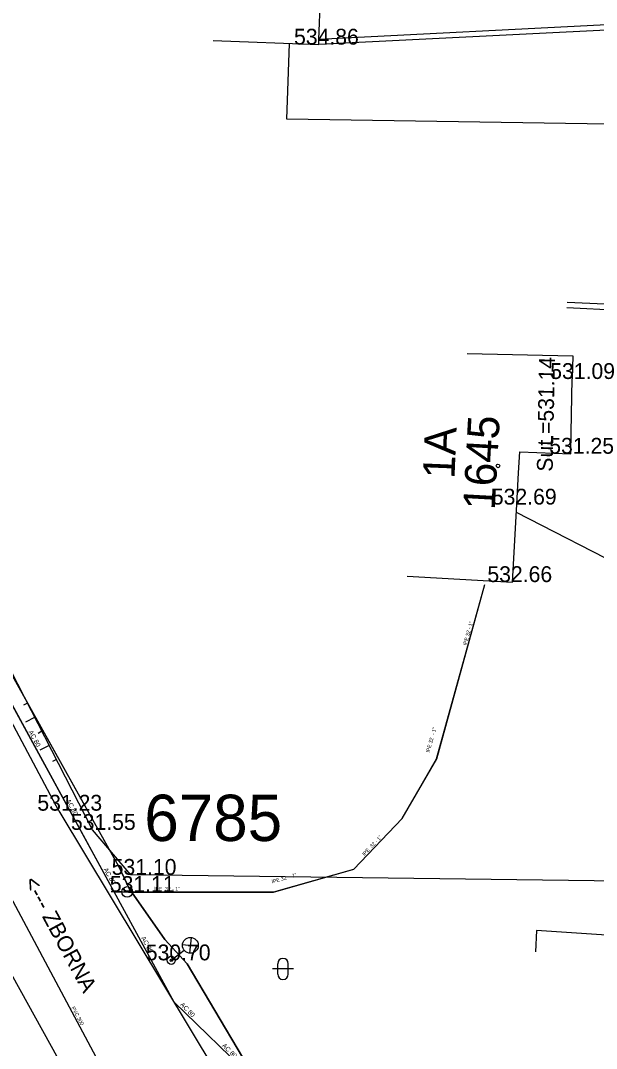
# Model space of a CAD drawing. Extents: x -669393 to -668650, y -1126925 to -1126294.
# Drawn here: x -669014.21 to -668986.94, y -1126777.26 to -1126728.57 of the extents above; entities that cross this region are included whole.
import ezdxf

# ---------------------------------------------------------------- set-up
doc = ezdxf.new("R2010")
doc.units = 0
for name, color, linetype in [('G_Bod_tecka', 7, 'Continuous'), ('G_Bod_vyska', 7, 'Continuous'), ('G_Budovy-znacky', 7, 'Continuous'), ('G_Budovy_Objekty', 7, 'Continuous'), ('G_Budovy_vstupy', 7, 'Continuous'), ('G_Cisla_orientacni', 7, 'Continuous'), ('G_Cisla_popisna', 7, 'Continuous'), ('G_Objekty_technicke', 7, 'Continuous'), ('G_Plochy_zpevnene', 7, 'Continuous'), ('G_Ploty', 7, 'Continuous'), ('G_Poznamky_odkaz', 7, 'Continuous'), ('G_Site-vodovod', 7, 'Continuous'), ('G_Vyskove_srafy', 7, 'Continuous'), ('G_Z_ELsilove_podz_kotovane', 7, 'Continuous'), ('G_Z_KANAL_podz_kotovane', 7, 'Continuous'), ('G_Z_PLYNY_podz_priblizne', 7, 'Continuous'), ('G_Z_SPOJE_podz_geodeticky', 7, 'Continuous'), ('G_Z_SPOJE_podz_kotovane', 7, 'Continuous'), ('G_Z_SPOJE_podz_priblizne', 7, 'Continuous'), ('G_Z_VODA_podz_kotovane', 7, 'Continuous'), ('G_Zelen-Znacky', 7, 'Continuous'), ('Vrstva 1', 7, 'Continuous'), ('Vrstva 12', 7, 'Continuous'), ('Vrstva 25', 7, 'Continuous'), ('Vrstva 27', 7, 'Continuous'), ('Vrstva 3', 7, 'Continuous'), ('Vrstva 4', 7, 'Continuous'), ('Vrstva 6', 7, 'Continuous'), ('Vrstva 62', 7, 'Continuous')]:
    doc.layers.add(name, color=color, linetype=linetype)

msp = doc.modelspace()

# ---------------------------------------------------------------- linework, layer by layer
at = {"layer": 'G_Bod_tecka'}
for p, q in [((-669000.08, -1126729.71), (-669000.08, -1126729.71)), ((-668988.08, -1126745.55), (-668988.08, -1126745.55)), ((-668988.15, -1126749.09), (-668988.15, -1126749.09)), ((-668990.71, -1126751.5), (-668990.71, -1126751.5)), ((-668990.91, -1126755.17), (-668990.91, -1126755.17)), ((-669012.39, -1126766), (-669012.39, -1126766)), ((-669010.8, -1126766.91), (-669010.8, -1126766.91)), ((-669008.99, -1126769.04), (-669008.99, -1126769.04)), ((-669009.16, -1126769.85), (-669009.16, -1126769.85)), ((-669007.07, -1126773.09), (-669007.07, -1126773.09))]:
    msp.add_line(p, q, dxfattribs=at)
at = {"layer": 'G_Budovy-znacky'}
msp.add_circle((-668991.6, -1126749.67), 0.0875, dxfattribs=at)
at = {"layer": 'G_Budovy_Objekty'}
for p, q in [((-669000.08, -1126729.46), (-668999.64, -1126718.94)), ((-669000.08, -1126729.71), (-669000.08, -1126729.46)), ((-669005.08, -1126729.51), (-669000.08, -1126729.71)), ((-668993.06, -1126744.35), (-668988.06, -1126744.45)), ((-668988.06, -1126744.45), (-668988.08, -1126745.55)), ((-668988.15, -1126749.09), (-668988.13, -1126748.09)), ((-668990.63, -1126750), (-668990.57, -1126749)), ((-668990.57, -1126749), (-668988.15, -1126749.09)), ((-668990.91, -1126755.17), (-668990.71, -1126751.5)), ((-668995.9, -1126754.89), (-668990.91, -1126755.17))]:
    msp.add_line(p, q, dxfattribs=at)
at = {"layer": 'G_Budovy_vstupy'}
for p, q in [((-668988.13, -1126748.09), (-668988.08, -1126745.55)), ((-668990.71, -1126751.5), (-668990.63, -1126750))]:
    msp.add_line(p, q, dxfattribs=at)
at = {"layer": 'G_Objekty_technicke'}
for points in [[(-669006.538, -1126772.335), (-669005.793, -1126772.425)], [(-669006.121, -1126772.008), (-669006.21, -1126772.752)], [(-669007.07, -1126773.09), (-669006.46, -1126772.611)]]:
    msp.add_lwpolyline(points, dxfattribs=at)
for centre, radius in [((-669006.166, -1126772.38), 0.375), ((-669007.07, -1126773.09), 0.19), ((-669007.07, -1126773.09), 0.05)]:
    msp.add_circle(centre, radius, dxfattribs=at)
at = {"layer": 'G_Plochy_zpevnene'}
for p, q in [((-669012.39, -1126766), (-669002.18, -1126783)), ((-669005.94, -1126789.45), (-669016.35, -1126770.66))]:
    msp.add_line(p, q, dxfattribs=at)
msp.add_lwpolyline([(-669012.39, -1126766), (-669017.9, -1126755.66)], dxfattribs=at)
at = {"layer": 'G_Ploty'}
for p, q in [((-668981.91, -1126728.54), (-669000.08, -1126729.46)), ((-668981.69, -1126728.78), (-669000.08, -1126729.71)), ((-668983.56, -1126742.15), (-668988.32, -1126741.92)), ((-668988.34, -1126742.17), (-668983.59, -1126742.4)), ((-669010.8, -1126766.91), (-669016.73, -1126755.36)), ((-669008.99, -1126769.04), (-669010.8, -1126766.91)), ((-668985.43, -1126769.34), (-669008.99, -1126769.04))]:
    msp.add_line(p, q, dxfattribs=at)
at = {"layer": 'G_Site-vodovod'}
for points in [[(-669009.41, -1126769.85), (-669009.91, -1126769.85)], [(-669008.91, -1126769.85), (-669008.41, -1126769.85)]]:
    msp.add_lwpolyline(points, dxfattribs=at)
msp.add_circle((-669009.16, -1126769.85), 0.25, dxfattribs=at)
at = {"layer": 'G_Vyskove_srafy'}
for points in [[(-669013.88, -1126760.91), (-669014.06, -1126761)], [(-669013.54, -1126761.58), (-669013.98, -1126761.81)], [(-669013.2, -1126762.24), (-669013.38, -1126762.34)], [(-669012.85, -1126762.91), (-669013.3, -1126763.14)], [(-669012.51, -1126763.58), (-669012.69, -1126763.67)]]:
    msp.add_lwpolyline(points, dxfattribs=at)
at = {"layer": 'G_Z_ELsilove_podz_kotovane'}
msp.add_lwpolyline([(-668991.15, -1126787.71), (-668992.47, -1126784.68), (-668992.94, -1126784.14), (-668993.85, -1126784), (-668994.99, -1126783.88), (-668997.24, -1126783.28), (-668999.66, -1126783.12), (-669000.56, -1126782.76), (-669001.95, -1126780.63), (-669003.7, -1126777.68), (-669006.31, -1126773.26), (-669007.38, -1126772.1), (-669009.06, -1126769.68), (-669009.55, -1126768.64), (-669025.04, -1126740.9), (-669039.34, -1126713.66), (-669057.59, -1126688.86), (-669057.53, -1126686.66), (-669073.8, -1126662.04), (-669088.6, -1126634.97), (-669111.98, -1126614.96), (-669163.86, -1126582.84), (-669189.05, -1126566.12), (-669226.41, -1126541.64)], dxfattribs=at)
at = {"layer": 'G_Z_KANAL_podz_kotovane'}
msp.add_lwpolyline([(-669021.5, -1126757.31), (-669019.78, -1126760.55), (-669002.4, -1126793.12), (-668998.38, -1126800.66), (-668997.87, -1126801.61)], dxfattribs=at)
at = {"layer": 'G_Z_PLYNY_podz_priblizne'}
msp.add_lwpolyline([(-668983.17, -1126772.12), (-668989.77, -1126771.68), (-668989.83, -1126772.68)], dxfattribs=at)
at = {"layer": 'G_Z_SPOJE_podz_geodeticky'}
for points in [[(-669001.6, -1126733.24), (-669001.48, -1126729.66)], [(-668982.59, -1126754.6), (-668982.04, -1126748.5), (-668981.76, -1126746.81), (-668980.27, -1126733.58), (-669001.6, -1126733.24)], [(-668982.59, -1126754.6), (-668985.31, -1126754.66), (-668990.73, -1126751.88)]]:
    msp.add_lwpolyline(points, dxfattribs=at)
at = {"layer": 'G_Z_SPOJE_podz_kotovane'}
for points in [[(-669001.6, -1126733.24), (-669001.48, -1126729.66)], [(-668982.59, -1126754.6), (-668982.04, -1126748.5), (-668981.76, -1126746.81), (-668980.27, -1126733.58), (-669001.6, -1126733.24)], [(-668982.59, -1126754.6), (-668985.31, -1126754.66), (-668990.73, -1126751.88)]]:
    msp.add_lwpolyline(points, dxfattribs=at)
at = {"layer": 'G_Z_SPOJE_podz_priblizne'}
for points in [[(-669001.6, -1126733.24), (-669001.48, -1126729.66)], [(-668982.59, -1126754.6), (-668982.04, -1126748.5), (-668981.76, -1126746.81), (-668980.27, -1126733.58), (-669001.6, -1126733.24)], [(-668982.59, -1126754.6), (-668985.31, -1126754.66), (-668990.73, -1126751.88)]]:
    msp.add_lwpolyline(points, dxfattribs=at)
at = {"layer": 'G_Z_VODA_podz_kotovane'}
for points in [[(-668985.62, -1126791.74), (-668992.01, -1126788.5), (-668997.53, -1126784.21), (-669003.22, -1126778.68), (-669006.93, -1126775.07), (-669009.78, -1126769.85), (-669016.27, -1126757.96), (-669026.17, -1126739.37), (-669033.16, -1126727.07), (-669036.74, -1126721.2), (-669037.32, -1126720.23), (-669038.2, -1126718.75), (-669038.67, -1126717.89)], [(-669009.78, -1126769.85), (-669009.1, -1126769.85), (-669008.97, -1126769.85), (-669002.22, -1126769.85), (-668998.42, -1126768.77), (-668996.14, -1126766.37), (-668994.5, -1126763.54), (-668992.22, -1126755.28)]]:
    msp.add_lwpolyline(points, dxfattribs=at)
at = {"layer": 'G_Zelen-Znacky'}
for points in [[(-669002.03, -1126773.75), (-669002.03, -1126773.25)], [(-669001.53, -1126773.75), (-669001.53, -1126773.25)], [(-669001.28, -1126773.5), (-669002.28, -1126773.5)]]:
    msp.add_lwpolyline(points, dxfattribs=at)
for centre, start, end in [((-669001.78, -1126773.25), 0, 180), ((-669001.78, -1126773.75), 180, 0)]:
    msp.add_arc(centre, 0.25, start, end, dxfattribs=at)
at = {"layer": 'Vrstva 1'}
msp.add_line((-669009.55, -1126768.64), (-669009.55, -1126768.64), dxfattribs=at)
at = {"layer": 'Vrstva 12'}
msp.add_lwpolyline([(-669021.5, -1126757.31), (-669019.78, -1126760.55), (-669002.4, -1126793.125), (-668998.377, -1126800.659), (-668997.87, -1126801.61)], dxfattribs=at)
at = {"layer": 'Vrstva 25'}
msp.add_lwpolyline([(-669009.778, -1126769.852), (-669009.1, -1126769.854), (-669008.966, -1126769.854), (-669002.225, -1126769.854), (-668998.419, -1126768.766), (-668996.136, -1126766.373), (-668994.505, -1126763.545), (-668992.221, -1126755.279)], dxfattribs=at)
at = {"layer": 'Vrstva 27'}
msp.add_lwpolyline([(-668985.623, -1126791.742), (-668992.014, -1126788.499), (-668997.526, -1126784.214), (-669003.219, -1126778.678), (-669006.931, -1126775.068), (-669009.778, -1126769.852), (-669016.269, -1126757.96), (-669026.168, -1126739.368), (-669033.16, -1126727.07), (-669036.741, -1126721.201), (-669037.32, -1126720.228), (-669038.2, -1126718.75), (-669038.665, -1126717.892)], dxfattribs=at)
at = {"layer": 'Vrstva 6'}
msp.add_line((-669009.1, -1126769.854), (-669009.1, -1126769.854), dxfattribs=at)
at = {"layer": 'Vrstva 62'}
for p, q in [((-669009.55, -1126768.64), (-669025.04, -1126740.9)), ((-669009.06, -1126769.68), (-669009.55, -1126768.64)), ((-669009.55, -1126768.64), (-669009.06, -1126769.68)), ((-669007.38, -1126772.1), (-669009.06, -1126769.68)), ((-669009.06, -1126769.68), (-669007.38, -1126772.1)), ((-669006.31, -1126773.26), (-669007.38, -1126772.1)), ((-669007.38, -1126772.1), (-669006.31, -1126773.26)), ((-669003.7, -1126777.68), (-669006.31, -1126773.26)), ((-669006.31, -1126773.26), (-669003.7, -1126777.68))]:
    msp.add_line(p, q, dxfattribs=at)

# ---------------------------------------------------------------- texts
at = {"layer": 'G_Bod_vyska'}
for s, p in [('534.86', (-669001.258, -1126729.71)), ('531.09', (-668989.126, -1126745.55)), ('531.25', (-668989.172, -1126749.09)), ('532.69', (-668991.89, -1126751.5)), ('532.66', (-668992.102, -1126755.17)), ('531.23', (-669013.412, -1126766)), ('531.55', (-669011.822, -1126766.91)), ('531.10', (-669009.892, -1126769.04)), ('531.11', (-669009.979, -1126769.85)), ('530.70', (-669008.277, -1126773.09))]:
    msp.add_text(s, height=0.75, dxfattribs=at).set_placement(p)
at = {"layer": 'G_Cisla_orientacni'}
msp.add_text('1A', height=1.5, rotation=87.6291, dxfattribs=at).set_placement((-668993.661, -1126750.295))
at = {"layer": 'G_Cisla_popisna'}
msp.add_text('1645', height=1.5, rotation=86.8613, dxfattribs=at).set_placement((-668991.756, -1126751.775))
at = {"layer": 'G_Poznamky_odkaz'}
for s, rotation, p in [('Sut.=531.14', 88.8723, (-668989.01, -1126749.946)), ('<--- ZBORNA', 298.3262, (-669014.09, -1126769.366))]:
    msp.add_text(s, height=0.75, rotation=rotation, dxfattribs=at).set_placement(p)
at = {"layer": 'Vrstva 3'}
msp.add_text('PVC 300', height=0.1755, rotation=298.0545, dxfattribs=at).set_placement((-669011.807, -1126775.335))
at = {"layer": 'Vrstva 4'}
for s, height, rotation, p in [('lPE 32 - 1"', 0.17551, 74.5939, (-668993.086, -1126758.173)), ('lPE 32  - 1"', 0.17551, 74.3578, (-668994.842, -1126763.254)), ('AC 80', 0.2194, 298.6567, (-669013.837, -1126762.267)), ('AC 80', 0.2194, 298.6567, (-669012.061, -1126765.521)), ('lPE  32 - 1"', 0.17551, 46.38, (-668997.919, -1126768.154)), ('AC 80', 0.2194, 298.6567, (-669010.285, -1126768.775)), ('lPE 32  - 1"', 0.17551, 16.1722, (-669002.281, -1126769.452)), ('AC 80', 0.2194, 298.5889, (-669008.509, -1126772.029)), ('AC 80', 0.2194, 314.3986, (-669006.665, -1126775.208)), ('AC 80', 0.2194, 315.7384, (-669004.686, -1126777.153))]:
    msp.add_text(s, height=height, rotation=rotation, dxfattribs=at).set_placement(p)
for s, height, p in [('6785', 2.1939, (-669008.347, -1126767.438)), ('lPE  32 - 1"', 0.17551, (-669007.877, -1126769.79))]:
    msp.add_text(s, height=height, dxfattribs=at).set_placement(p)

doc.saveas('drawing.dxf')
